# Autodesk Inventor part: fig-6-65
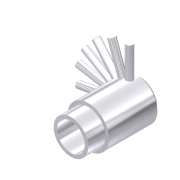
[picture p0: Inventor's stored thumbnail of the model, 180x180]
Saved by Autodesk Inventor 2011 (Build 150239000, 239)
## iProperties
Shininess: 77.0
Angle Display Precision: 2
Document Length Units: 11269
Document Angle Units: 11279
Document Time Units: 11290
Document Mass Units: 11283
Document Length Units Precision: 3
Document Angle Units Precision: 2
Compacted: True
Created: 2001-12
Part Number: fig-6-65
Document SubType Name: Modeling
Designer: Renu Muthoo
Density: 1 g/cm^3
Density: 0.0
Volumn: 0.0
Area: 0.0
PropertySet Name: Model Information
Control State: 0
Master: False
Checked Out: False
Author: Renu Muthoo
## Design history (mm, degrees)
sketch "Sketch2"
  geometry: L1 (-9.573, -4.327)-(-9.573, -5.327); L2 (-9.573, -5.327)-(-4.573, -5.327); L3 (-4.573, -5.327)-(-4.573, -6.327); L4 (-4.573, -6.327)-(9.427, -6.327); L5 (9.427, -6.327)-(10.427, -5.327); L6 (10.427, -5.327)-(10.427, -4.327); L7 (10.427, -4.327)-(-9.573, -4.327); L8 (-13.687, -0.327)-(14, -0.327)
  constraints: 16 end point, 5 parallel, 1 perpendicular, 1 vertical
  dimensions: "d9" = 20 distance of L6.end L1.start; "d10" = 5 distance of L1.end L2.end; "d11" = 12 diameter of L4 L8; "d12" = 10 diameter of L2 L8; "d13" = 8 diameter of L7 L8; "d14" = 45 deg angle of L5 L4; "d15" = 1 horizontal distance of L5.end L4.end
revolve "Revolution2" sketch "Sketch2" stored, may be unused: angle "d16" = 90 deg
workplane "Work Plane1"
workplane "Work Plane2"
sketch "Sketch3"
  geometry: L1 (-4, 8)-(4, 8) reference; C1 r 1 at (-0.098, 5)
  constraints: 1 centre point
  dimensions: "d18" = 3 distance from line of L1 C1.centre; "d19" = 2 diameter of C1
extrude "Extrusion1" join sketch "Sketch3" distance "d20" = 10; taper "d21" = 0 deg
pattern_circular "Circular Pattern3" dims angle "d29" = 20 deg
body "Solid1"
other parameters: "d17" = -1
